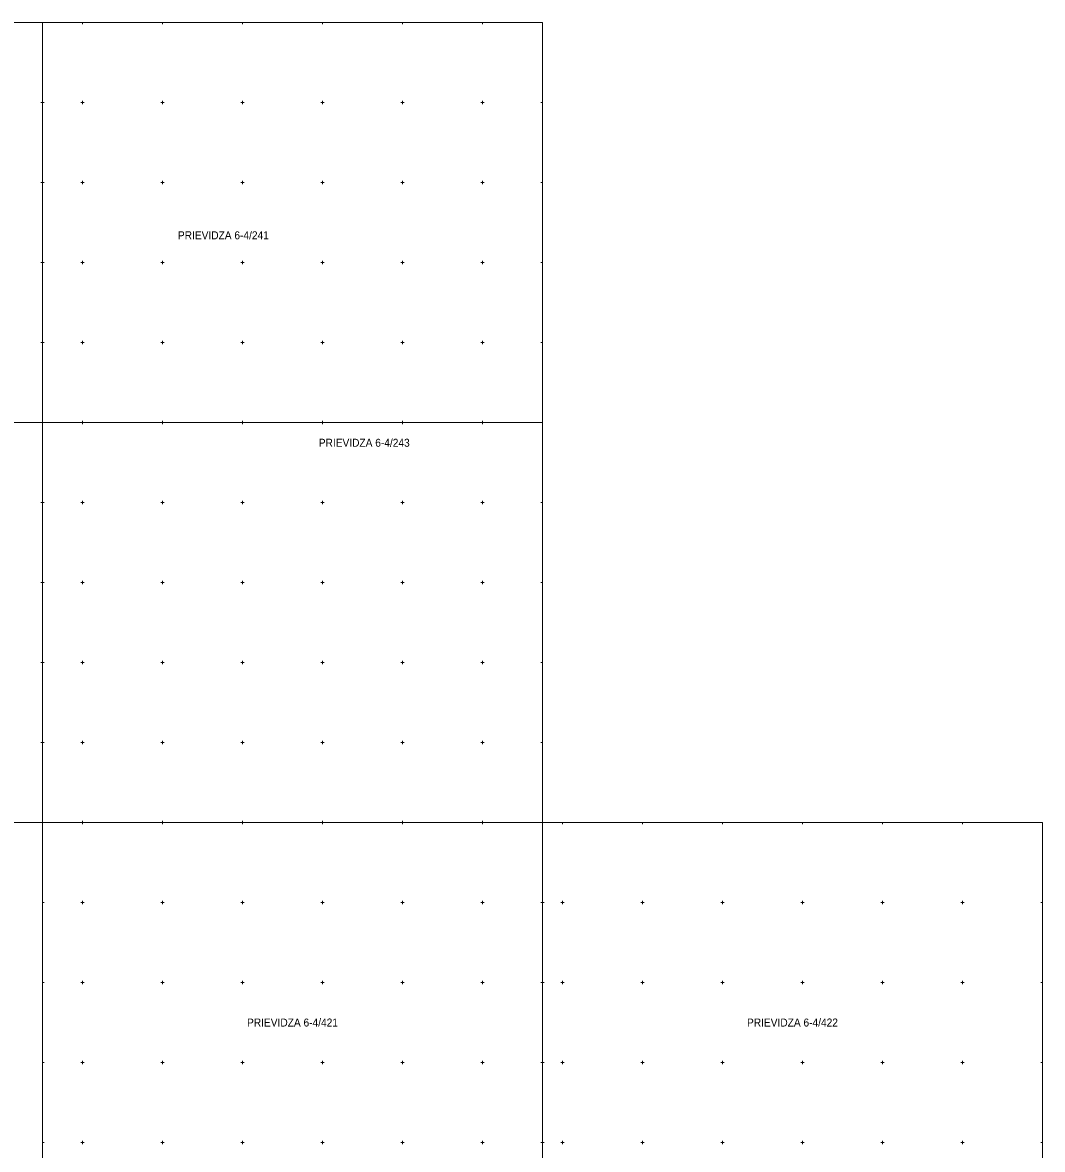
# Model space of a CAD drawing. Extents: x -46688 to -46438, y -123000 to -122825.
# Drawn here: x -46563.8 to -46500, y -122920.4 to -122850 of the extents above; entities that cross this region are included whole.
import ezdxf
from ezdxf.enums import TextEntityAlignment as Align

# ---------------------------------------------------------------- set-up
doc = ezdxf.new("R2010")
doc.units = 0
doc.header["$LTSCALE"] = 0.2
doc.layers.add('17', color=7, linetype='Continuous', lineweight=13)
doc.layers.add('18', color=7, linetype='Continuous', lineweight=13)
doc.layers.add('19', color=7, linetype='Continuous')

msp = doc.modelspace()

# ---------------------------------------------------------------- linework, layer by layer
at = {"layer": '17'}
for points in [[(-46562.5, -122850), (-46593.75, -122850), (-46593.75, -122875), (-46562.5, -122875)], [(-46531.25, -122850), (-46562.5, -122850), (-46562.5, -122875), (-46531.25, -122875)], [(-46562.5, -122875), (-46593.75, -122875), (-46593.75, -122900), (-46562.5, -122900)], [(-46531.25, -122875), (-46562.5, -122875), (-46562.5, -122900), (-46531.25, -122900)], [(-46531.25, -122900), (-46562.5, -122900), (-46562.5, -122925), (-46531.25, -122925)], [(-46500, -122900), (-46531.25, -122900), (-46531.25, -122925), (-46500, -122925)]]:
    msp.add_lwpolyline(points, close=True, dxfattribs=at)
at = {"layer": '18'}
for p, q in [((-46560, -122850), (-46560, -122850.1)), ((-46560, -122850), (-46560, -122850.1)), ((-46560, -122850), (-46560, -122850.1)), ((-46560, -122850), (-46560, -122850.1)), ((-46555, -122850), (-46555, -122850.1)), ((-46555, -122850), (-46555, -122850.1)), ((-46555, -122850), (-46555, -122850.1)), ((-46555, -122850), (-46555, -122850.1)), ((-46550, -122850), (-46550, -122850.1)), ((-46550, -122850), (-46550, -122850.1)), ((-46550, -122850), (-46550, -122850.1)), ((-46550, -122850), (-46550, -122850.1)), ((-46545, -122850), (-46545, -122850.1)), ((-46545, -122850), (-46545, -122850.1)), ((-46545, -122850), (-46545, -122850.1)), ((-46545, -122850), (-46545, -122850.1)), ((-46540, -122850), (-46540, -122850.1)), ((-46540, -122850), (-46540, -122850.1)), ((-46540, -122850), (-46540, -122850.1)), ((-46540, -122850), (-46540, -122850.1)), ((-46535, -122850), (-46535, -122850.1)), ((-46535, -122850), (-46535, -122850.1)), ((-46535, -122850), (-46535, -122850.1)), ((-46535, -122850), (-46535, -122850.1)), ((-46562.5, -122855), (-46562.6, -122855)), ((-46562.5, -122855), (-46562.4, -122855)), ((-46559.9, -122855), (-46560.1, -122855)), ((-46560, -122854.9), (-46560, -122855.1)), ((-46554.9, -122855), (-46555.1, -122855)), ((-46555, -122854.9), (-46555, -122855.1)), ((-46549.9, -122855), (-46550.1, -122855)), ((-46550, -122854.9), (-46550, -122855.1)), ((-46544.9, -122855), (-46545.1, -122855)), ((-46545, -122854.9), (-46545, -122855.1)), ((-46539.9, -122855), (-46540.1, -122855)), ((-46540, -122854.9), (-46540, -122855.1)), ((-46534.9, -122855), (-46535.1, -122855)), ((-46535, -122854.9), (-46535, -122855.1)), ((-46531.25, -122855), (-46531.35, -122855)), ((-46562.5, -122860), (-46562.6, -122860)), ((-46562.5, -122860), (-46562.4, -122860)), ((-46559.9, -122860), (-46560.1, -122860)), ((-46560, -122859.9), (-46560, -122860.1)), ((-46554.9, -122860), (-46555.1, -122860)), ((-46555, -122859.9), (-46555, -122860.1)), ((-46549.9, -122860), (-46550.1, -122860)), ((-46550, -122859.9), (-46550, -122860.1)), ((-46544.9, -122860), (-46545.1, -122860)), ((-46545, -122859.9), (-46545, -122860.1)), ((-46539.9, -122860), (-46540.1, -122860)), ((-46540, -122859.9), (-46540, -122860.1)), ((-46534.9, -122860), (-46535.1, -122860)), ((-46535, -122859.9), (-46535, -122860.1)), ((-46531.25, -122860), (-46531.35, -122860)), ((-46562.5, -122865), (-46562.6, -122865)), ((-46562.5, -122865), (-46562.4, -122865)), ((-46559.9, -122865), (-46560.1, -122865)), ((-46560, -122864.9), (-46560, -122865.1)), ((-46554.9, -122865), (-46555.1, -122865)), ((-46555, -122864.9), (-46555, -122865.1)), ((-46549.9, -122865), (-46550.1, -122865)), ((-46550, -122864.9), (-46550, -122865.1)), ((-46544.9, -122865), (-46545.1, -122865)), ((-46545, -122864.9), (-46545, -122865.1)), ((-46539.9, -122865), (-46540.1, -122865)), ((-46540, -122864.9), (-46540, -122865.1)), ((-46534.9, -122865), (-46535.1, -122865)), ((-46535, -122864.9), (-46535, -122865.1)), ((-46531.25, -122865), (-46531.35, -122865)), ((-46562.5, -122870), (-46562.6, -122870)), ((-46562.5, -122870), (-46562.4, -122870)), ((-46559.9, -122870), (-46560.1, -122870)), ((-46560, -122869.9), (-46560, -122870.1)), ((-46554.9, -122870), (-46555.1, -122870)), ((-46555, -122869.9), (-46555, -122870.1)), ((-46549.9, -122870), (-46550.1, -122870)), ((-46550, -122869.9), (-46550, -122870.1)), ((-46544.9, -122870), (-46545.1, -122870)), ((-46545, -122869.9), (-46545, -122870.1)), ((-46539.9, -122870), (-46540.1, -122870)), ((-46540, -122869.9), (-46540, -122870.1)), ((-46534.9, -122870), (-46535.1, -122870)), ((-46535, -122869.9), (-46535, -122870.1)), ((-46531.25, -122870), (-46531.35, -122870)), ((-46560, -122875), (-46560, -122874.9)), ((-46560, -122875), (-46560, -122874.9)), ((-46560, -122875), (-46560, -122874.9)), ((-46560, -122875), (-46560, -122874.9)), ((-46560, -122875), (-46560, -122875.1)), ((-46560, -122875), (-46560, -122875.1)), ((-46560, -122875), (-46560, -122875.1)), ((-46560, -122875), (-46560, -122875.1)), ((-46555, -122875), (-46555, -122874.9)), ((-46555, -122875), (-46555, -122874.9)), ((-46555, -122875), (-46555, -122874.9)), ((-46555, -122875), (-46555, -122874.9)), ((-46555, -122875), (-46555, -122875.1)), ((-46555, -122875), (-46555, -122875.1)), ((-46555, -122875), (-46555, -122875.1)), ((-46555, -122875), (-46555, -122875.1)), ((-46550, -122875), (-46550, -122874.9)), ((-46550, -122875), (-46550, -122874.9)), ((-46550, -122875), (-46550, -122874.9)), ((-46550, -122875), (-46550, -122874.9)), ((-46550, -122875), (-46550, -122875.1)), ((-46550, -122875), (-46550, -122875.1)), ((-46550, -122875), (-46550, -122875.1)), ((-46550, -122875), (-46550, -122875.1)), ((-46545, -122875), (-46545, -122874.9)), ((-46545, -122875), (-46545, -122874.9)), ((-46545, -122875), (-46545, -122874.9)), ((-46545, -122875), (-46545, -122874.9)), ((-46545, -122875), (-46545, -122875.1)), ((-46545, -122875), (-46545, -122875.1)), ((-46545, -122875), (-46545, -122875.1)), ((-46545, -122875), (-46545, -122875.1)), ((-46540, -122875), (-46540, -122874.9)), ((-46540, -122875), (-46540, -122874.9)), ((-46540, -122875), (-46540, -122874.9)), ((-46540, -122875), (-46540, -122874.9)), ((-46540, -122875), (-46540, -122875.1)), ((-46540, -122875), (-46540, -122875.1)), ((-46540, -122875), (-46540, -122875.1)), ((-46540, -122875), (-46540, -122875.1)), ((-46535, -122875), (-46535, -122874.9)), ((-46535, -122875), (-46535, -122874.9)), ((-46535, -122875), (-46535, -122874.9)), ((-46535, -122875), (-46535, -122874.9)), ((-46535, -122875), (-46535, -122875.1)), ((-46535, -122875), (-46535, -122875.1)), ((-46535, -122875), (-46535, -122875.1)), ((-46535, -122875), (-46535, -122875.1)), ((-46562.5, -122880), (-46562.6, -122880)), ((-46562.5, -122880), (-46562.4, -122880)), ((-46559.9, -122880), (-46560.1, -122880)), ((-46560, -122879.9), (-46560, -122880.1)), ((-46554.9, -122880), (-46555.1, -122880)), ((-46555, -122879.9), (-46555, -122880.1)), ((-46549.9, -122880), (-46550.1, -122880)), ((-46550, -122879.9), (-46550, -122880.1)), ((-46544.9, -122880), (-46545.1, -122880)), ((-46545, -122879.9), (-46545, -122880.1)), ((-46539.9, -122880), (-46540.1, -122880)), ((-46540, -122879.9), (-46540, -122880.1)), ((-46534.9, -122880), (-46535.1, -122880)), ((-46535, -122879.9), (-46535, -122880.1)), ((-46531.25, -122880), (-46531.35, -122880)), ((-46560, -122884.9), (-46560, -122885.1)), ((-46555, -122884.9), (-46555, -122885.1)), ((-46550, -122884.9), (-46550, -122885.1)), ((-46545, -122884.9), (-46545, -122885.1)), ((-46540, -122884.9), (-46540, -122885.1)), ((-46535, -122884.9), (-46535, -122885.1)), ((-46562.5, -122885), (-46562.6, -122885)), ((-46562.5, -122885), (-46562.4, -122885)), ((-46559.9, -122885), (-46560.1, -122885)), ((-46554.9, -122885), (-46555.1, -122885)), ((-46549.9, -122885), (-46550.1, -122885)), ((-46544.9, -122885), (-46545.1, -122885)), ((-46539.9, -122885), (-46540.1, -122885)), ((-46534.9, -122885), (-46535.1, -122885)), ((-46531.25, -122885), (-46531.35, -122885)), ((-46560, -122889.9), (-46560, -122890.1)), ((-46555, -122889.9), (-46555, -122890.1)), ((-46550, -122889.9), (-46550, -122890.1)), ((-46545, -122889.9), (-46545, -122890.1)), ((-46540, -122889.9), (-46540, -122890.1)), ((-46535, -122889.9), (-46535, -122890.1)), ((-46562.5, -122890), (-46562.6, -122890)), ((-46562.5, -122890), (-46562.4, -122890)), ((-46559.9, -122890), (-46560.1, -122890)), ((-46554.9, -122890), (-46555.1, -122890)), ((-46549.9, -122890), (-46550.1, -122890)), ((-46544.9, -122890), (-46545.1, -122890)), ((-46539.9, -122890), (-46540.1, -122890)), ((-46534.9, -122890), (-46535.1, -122890)), ((-46531.25, -122890), (-46531.35, -122890)), ((-46562.5, -122895), (-46562.6, -122895)), ((-46562.5, -122895), (-46562.4, -122895)), ((-46559.9, -122895), (-46560.1, -122895)), ((-46560, -122894.9), (-46560, -122895.1)), ((-46554.9, -122895), (-46555.1, -122895)), ((-46555, -122894.9), (-46555, -122895.1)), ((-46549.9, -122895), (-46550.1, -122895)), ((-46550, -122894.9), (-46550, -122895.1)), ((-46544.9, -122895), (-46545.1, -122895)), ((-46545, -122894.9), (-46545, -122895.1)), ((-46539.9, -122895), (-46540.1, -122895)), ((-46540, -122894.9), (-46540, -122895.1)), ((-46534.9, -122895), (-46535.1, -122895)), ((-46535, -122894.9), (-46535, -122895.1)), ((-46531.25, -122895), (-46531.35, -122895)), ((-46560, -122900), (-46560, -122899.9)), ((-46560, -122900), (-46560, -122899.9)), ((-46560, -122900), (-46560, -122899.9)), ((-46560, -122900), (-46560, -122899.9)), ((-46560, -122900), (-46560, -122900.1)), ((-46560, -122900), (-46560, -122900.1)), ((-46560, -122900), (-46560, -122900.1)), ((-46560, -122900), (-46560, -122900.1)), ((-46555, -122900), (-46555, -122899.9)), ((-46555, -122900), (-46555, -122899.9)), ((-46555, -122900), (-46555, -122899.9)), ((-46555, -122900), (-46555, -122899.9)), ((-46555, -122900), (-46555, -122900.1)), ((-46555, -122900), (-46555, -122900.1)), ((-46555, -122900), (-46555, -122900.1)), ((-46555, -122900), (-46555, -122900.1)), ((-46550, -122900), (-46550, -122899.9)), ((-46550, -122900), (-46550, -122899.9)), ((-46550, -122900), (-46550, -122899.9)), ((-46550, -122900), (-46550, -122899.9)), ((-46550, -122900), (-46550, -122900.1)), ((-46550, -122900), (-46550, -122900.1)), ((-46550, -122900), (-46550, -122900.1)), ((-46550, -122900), (-46550, -122900.1)), ((-46545, -122900), (-46545, -122899.9)), ((-46545, -122900), (-46545, -122899.9)), ((-46545, -122900), (-46545, -122899.9)), ((-46545, -122900), (-46545, -122899.9)), ((-46545, -122900), (-46545, -122900.1)), ((-46545, -122900), (-46545, -122900.1)), ((-46545, -122900), (-46545, -122900.1)), ((-46545, -122900), (-46545, -122900.1)), ((-46540, -122900), (-46540, -122899.9)), ((-46540, -122900), (-46540, -122899.9)), ((-46540, -122900), (-46540, -122899.9)), ((-46540, -122900), (-46540, -122899.9)), ((-46540, -122900), (-46540, -122900.1)), ((-46540, -122900), (-46540, -122900.1)), ((-46540, -122900), (-46540, -122900.1)), ((-46540, -122900), (-46540, -122900.1)), ((-46535, -122900), (-46535, -122899.9)), ((-46535, -122900), (-46535, -122899.9)), ((-46535, -122900), (-46535, -122899.9)), ((-46535, -122900), (-46535, -122899.9)), ((-46535, -122900), (-46535, -122900.1)), ((-46535, -122900), (-46535, -122900.1)), ((-46535, -122900), (-46535, -122900.1)), ((-46535, -122900), (-46535, -122900.1)), ((-46530, -122900), (-46530, -122900.1)), ((-46530, -122900), (-46530, -122900.1)), ((-46530, -122900), (-46530, -122900.1)), ((-46530, -122900), (-46530, -122900.1)), ((-46525, -122900), (-46525, -122900.1)), ((-46525, -122900), (-46525, -122900.1)), ((-46525, -122900), (-46525, -122900.1)), ((-46525, -122900), (-46525, -122900.1)), ((-46520, -122900), (-46520, -122900.1)), ((-46520, -122900), (-46520, -122900.1)), ((-46520, -122900), (-46520, -122900.1)), ((-46520, -122900), (-46520, -122900.1)), ((-46515, -122900), (-46515, -122900.1)), ((-46515, -122900), (-46515, -122900.1)), ((-46515, -122900), (-46515, -122900.1)), ((-46515, -122900), (-46515, -122900.1)), ((-46510, -122900), (-46510, -122900.1)), ((-46510, -122900), (-46510, -122900.1)), ((-46510, -122900), (-46510, -122900.1)), ((-46510, -122900), (-46510, -122900.1)), ((-46505, -122900), (-46505, -122900.1)), ((-46505, -122900), (-46505, -122900.1)), ((-46505, -122900), (-46505, -122900.1)), ((-46505, -122900), (-46505, -122900.1)), ((-46562.5, -122905), (-46562.4, -122905)), ((-46559.9, -122905), (-46560.1, -122905)), ((-46560, -122904.9), (-46560, -122905.1)), ((-46554.9, -122905), (-46555.1, -122905)), ((-46555, -122904.9), (-46555, -122905.1)), ((-46549.9, -122905), (-46550.1, -122905)), ((-46550, -122904.9), (-46550, -122905.1)), ((-46544.9, -122905), (-46545.1, -122905)), ((-46545, -122904.9), (-46545, -122905.1)), ((-46539.9, -122905), (-46540.1, -122905)), ((-46540, -122904.9), (-46540, -122905.1)), ((-46534.9, -122905), (-46535.1, -122905)), ((-46535, -122904.9), (-46535, -122905.1)), ((-46531.25, -122905), (-46531.35, -122905)), ((-46531.25, -122905), (-46531.15, -122905)), ((-46529.9, -122905), (-46530.1, -122905)), ((-46530, -122904.9), (-46530, -122905.1)), ((-46524.9, -122905), (-46525.1, -122905)), ((-46525, -122904.9), (-46525, -122905.1)), ((-46519.9, -122905), (-46520.1, -122905)), ((-46520, -122904.9), (-46520, -122905.1)), ((-46514.9, -122905), (-46515.1, -122905)), ((-46515, -122904.9), (-46515, -122905.1)), ((-46509.9, -122905), (-46510.1, -122905)), ((-46510, -122904.9), (-46510, -122905.1)), ((-46504.9, -122905), (-46505.1, -122905)), ((-46505, -122904.9), (-46505, -122905.1)), ((-46500, -122905), (-46500.1, -122905)), ((-46562.5, -122910), (-46562.4, -122910)), ((-46559.9, -122910), (-46560.1, -122910)), ((-46560, -122909.9), (-46560, -122910.1)), ((-46554.9, -122910), (-46555.1, -122910)), ((-46555, -122909.9), (-46555, -122910.1)), ((-46549.9, -122910), (-46550.1, -122910)), ((-46550, -122909.9), (-46550, -122910.1)), ((-46544.9, -122910), (-46545.1, -122910)), ((-46545, -122909.9), (-46545, -122910.1)), ((-46539.9, -122910), (-46540.1, -122910)), ((-46540, -122909.9), (-46540, -122910.1)), ((-46534.9, -122910), (-46535.1, -122910)), ((-46535, -122909.9), (-46535, -122910.1)), ((-46531.25, -122910), (-46531.35, -122910)), ((-46531.25, -122910), (-46531.15, -122910)), ((-46529.9, -122910), (-46530.1, -122910)), ((-46530, -122909.9), (-46530, -122910.1)), ((-46524.9, -122910), (-46525.1, -122910)), ((-46525, -122909.9), (-46525, -122910.1)), ((-46519.9, -122910), (-46520.1, -122910)), ((-46520, -122909.9), (-46520, -122910.1)), ((-46514.9, -122910), (-46515.1, -122910)), ((-46515, -122909.9), (-46515, -122910.1)), ((-46509.9, -122910), (-46510.1, -122910)), ((-46510, -122909.9), (-46510, -122910.1)), ((-46504.9, -122910), (-46505.1, -122910)), ((-46505, -122909.9), (-46505, -122910.1)), ((-46500, -122910), (-46500.1, -122910)), ((-46562.5, -122915), (-46562.4, -122915)), ((-46559.9, -122915), (-46560.1, -122915)), ((-46560, -122914.9), (-46560, -122915.1)), ((-46554.9, -122915), (-46555.1, -122915)), ((-46555, -122914.9), (-46555, -122915.1)), ((-46549.9, -122915), (-46550.1, -122915)), ((-46550, -122914.9), (-46550, -122915.1)), ((-46544.9, -122915), (-46545.1, -122915)), ((-46545, -122914.9), (-46545, -122915.1)), ((-46539.9, -122915), (-46540.1, -122915)), ((-46540, -122914.9), (-46540, -122915.1)), ((-46534.9, -122915), (-46535.1, -122915)), ((-46535, -122914.9), (-46535, -122915.1)), ((-46531.25, -122915), (-46531.35, -122915)), ((-46531.25, -122915), (-46531.15, -122915)), ((-46529.9, -122915), (-46530.1, -122915)), ((-46530, -122914.9), (-46530, -122915.1)), ((-46524.9, -122915), (-46525.1, -122915)), ((-46525, -122914.9), (-46525, -122915.1)), ((-46519.9, -122915), (-46520.1, -122915)), ((-46520, -122914.9), (-46520, -122915.1)), ((-46514.9, -122915), (-46515.1, -122915)), ((-46515, -122914.9), (-46515, -122915.1)), ((-46509.9, -122915), (-46510.1, -122915)), ((-46510, -122914.9), (-46510, -122915.1)), ((-46504.9, -122915), (-46505.1, -122915)), ((-46505, -122914.9), (-46505, -122915.1)), ((-46500, -122915), (-46500.1, -122915)), ((-46562.5, -122920), (-46562.4, -122920)), ((-46559.9, -122920), (-46560.1, -122920)), ((-46560, -122919.9), (-46560, -122920.1)), ((-46554.9, -122920), (-46555.1, -122920)), ((-46555, -122919.9), (-46555, -122920.1)), ((-46549.9, -122920), (-46550.1, -122920)), ((-46550, -122919.9), (-46550, -122920.1)), ((-46544.9, -122920), (-46545.1, -122920)), ((-46545, -122919.9), (-46545, -122920.1)), ((-46539.9, -122920), (-46540.1, -122920)), ((-46540, -122919.9), (-46540, -122920.1)), ((-46534.9, -122920), (-46535.1, -122920)), ((-46535, -122919.9), (-46535, -122920.1)), ((-46531.25, -122920), (-46531.35, -122920)), ((-46531.25, -122920), (-46531.15, -122920)), ((-46529.9, -122920), (-46530.1, -122920)), ((-46530, -122919.9), (-46530, -122920.1)), ((-46524.9, -122920), (-46525.1, -122920)), ((-46525, -122919.9), (-46525, -122920.1)), ((-46519.9, -122920), (-46520.1, -122920)), ((-46520, -122919.9), (-46520, -122920.1)), ((-46514.9, -122920), (-46515.1, -122920)), ((-46515, -122919.9), (-46515, -122920.1)), ((-46509.9, -122920), (-46510.1, -122920)), ((-46510, -122919.9), (-46510, -122920.1)), ((-46504.9, -122920), (-46505.1, -122920)), ((-46505, -122919.9), (-46505, -122920.1)), ((-46500, -122920), (-46500.1, -122920))]:
    msp.add_line(p, q, dxfattribs=at)

# ---------------------------------------------------------------- texts
at = {"layer": '19', "width": 0.95}
for s, p in [('PRIEVIDZA 6-4/241', (-46551.196, -122863.548)), ('PRIEVIDZA 6-4/243', (-46542.391, -122876.514)), ('PRIEVIDZA 6-4/421', (-46546.875, -122912.75)), ('PRIEVIDZA 6-4/422', (-46515.625, -122912.75))]:
    msp.add_text(s, height=0.5, dxfattribs=at).set_placement(p, align=Align.CENTER)

doc.saveas('drawing.dxf')
